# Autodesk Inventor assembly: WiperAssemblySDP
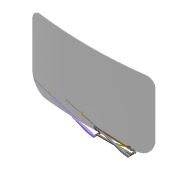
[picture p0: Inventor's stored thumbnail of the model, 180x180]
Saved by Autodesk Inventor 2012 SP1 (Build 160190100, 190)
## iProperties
Created: 2006-03
Part Number: WiperAssemblySDP
Document SubType Name: Assembly
Designer: debonom
Mass: 11755.5 g
Surface Area: 27652.3 cm^2
Volume: 10296.6 cm^3
Density: 1.14169 g/cm^3
Author: debonom
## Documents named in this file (9)
- D:\Backup\Autodesk Motion Files\Inv2012DynSim\WiperAssemblySDP.iam
- D:\Backup\Autodesk Motion Files\Inv2012DynSim\Parts\Bearings.ipt
- D:\Backup\Autodesk Motion Files\Inv2012DynSim\Sub-Assemblies\Motor_Crank_Asm.iam
- D:\Backup\Autodesk Motion Files\Inv2012DynSim\Sub-Assemblies\Complete_wiper_left_asm.iam
- D:\Backup\Autodesk Motion Files\Inv2012DynSim\Sub-Assemblies\Complete_wiper_right_asm.iam
- D:\Backup\Autodesk Motion Files\Inv2012DynSim\Parts\Crank_motor2.ipt
- D:\Backup\Autodesk Motion Files\Inv2012DynSim\Parts\Inter_Crank.ipt
- D:\Backup\Autodesk Motion Files\Inv2012DynSim\Parts\Windscreen.ipt
- D:\Backup\Autodesk Motion Files\Inv2012DynSim\Sub-Assemblies\Brush_asm_left.iam
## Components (8 placed, 8 different names)
1. Bearings:1 — Mate:1, Mate:2, Mate:3, Mate:9, Mate:11
2. Windscreen:1 — Mate:1, Mate:2, Mate:3
3. Motor_Crank_Asm:1 [sub-assembly]
4. Brush_asm_left:1 [sub-assembly] — Mate:4, Mate:5, Angle:2
5. Complete_wiper_left_asm:1 [sub-assembly] — Mate:4, Mate:5, Angle:2
6. Complete_wiper_right_asm:1 [sub-assembly] — Mate:9, Mate:11
7. Crank_motor2:1
8. Inter_Crank:1
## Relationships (8: Mate 7, Angle 1)
- Mate:1: Bearings:1 ↔ Windscreen:1
- Mate:2: Bearings:1 ↔ Windscreen:1
- Mate:3: Bearings:1 ↔ Windscreen:1
- Mate:4: Brush_asm_left:1 ↔ Complete_wiper_left_asm:1
- Mate:5: Brush_asm_left:1 ↔ Complete_wiper_left_asm:1
- Angle:2: Brush_asm_left:1 ↔ Complete_wiper_left_asm:1
- Mate:9: Bearings:1 ↔ Complete_wiper_right_asm:1
- Mate:11: Bearings:1 ↔ Complete_wiper_right_asm:1
